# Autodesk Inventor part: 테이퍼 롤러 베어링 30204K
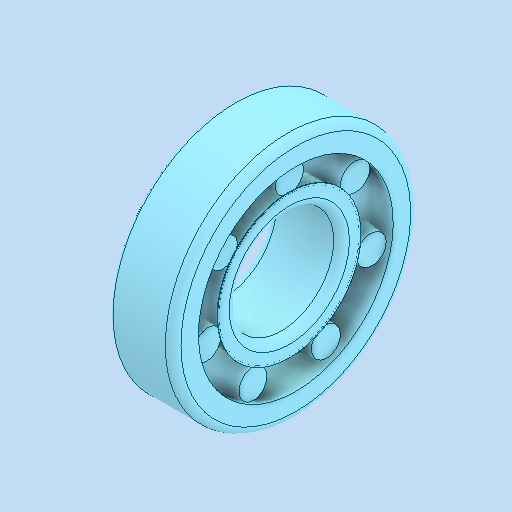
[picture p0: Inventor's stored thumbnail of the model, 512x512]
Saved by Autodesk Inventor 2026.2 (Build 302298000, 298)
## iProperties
Created: 2026-01
Part Number: 테이퍼 롤러 베어링 30204K
Material: 강철, 연강
Description: 테이퍼 롤러 베어링
Document SubType Name: Modeling
Designer: PC2-07
Density: 7.85 g/cm^3
Appearance: 기본값
Author: jhkim
Sending System: Autodesk Inventor 2026
Preprocessor: ST-DEVELOPER v20.1
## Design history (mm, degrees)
feature "Solid1"
feature "Solid1:1"
node "솔리드1"
node "솔리드2"
